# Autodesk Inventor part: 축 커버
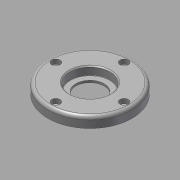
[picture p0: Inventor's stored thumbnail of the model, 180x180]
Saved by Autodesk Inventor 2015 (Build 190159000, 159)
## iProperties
Created: 2015-10
Part Number: 축 커버
Document SubType Name: Modeling
Designer: mdu
Density: 7.86 g/cm^3
Material: 강철, 연강
Appearance: 강철
Mass: 322.464 g
Surface Area: 133.703 cm^2
Volume: 41.026 cm^3
Author: mdu
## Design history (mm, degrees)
sketch "스케치1"
  geometry: C1 r 40 at (0, 0) reference; C2 r 26 at (0, 0) reference; 1 further point
  node "참조1"
  node "참조2"
extrude "돌출1" new body sketch "스케치1" distance "d0" = 10; taper "d1" = 0 deg
extrude "돌출2" join sketch "스케치1" distance "d2" = 3; taper "d3" = 0 deg
hole "구멍1" diameter "d6" = 27; stored, may be unused: countersink angle "d10" = 90 deg, drill point angle "d12" = 118 deg; dims "d4" = 10, "d5" = 10, "d7" = 6, "d8" = 38, "d9" = 8, "d11" = 8
sketch "스케치2"
  geometry: C1 r 20 at (0, 0); 1 further point
  constraints: 1 centre point, 1 coincident
  dimensions: "d13" = 40 diameter of C1
extrude "돌출3" cut sketch "스케치2" distance "d14" = 3; taper "d15" = 0 deg
sketch "스케치3"
  geometry: C1 r 1.621 at (0, 32.5) reference; 1 further point
hole "구멍2" sketch "스케치3" at (0, 32.5) diameter "d16" = 4.5; stored, may be unused: countersink angle "d20" = 90 deg, drill point angle "d22" = 118 deg; dims "d17" = 6, "d18" = 8, "d19" = 4.4, "d21" = 8
fillet "모깎기1" dims "d26" = 3, "d27" = 0.3
chamfer "모따기1" distance "d28" = 1; stored, may be unused: second distance "d29" = 2, angle "d30" = 45 deg
node "솔리드1"
pattern_circular "원형 패턴1" dims angle "d24" = 360 deg
node "참조3"
